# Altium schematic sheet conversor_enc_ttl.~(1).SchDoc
size A4
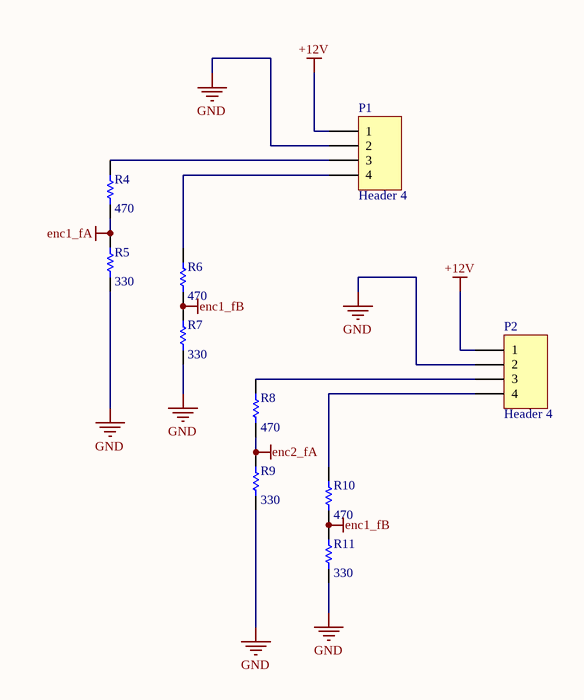
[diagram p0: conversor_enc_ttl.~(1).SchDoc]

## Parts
P1  Header 4  [HDR1X4]
P2  Header 4  [HDR1X4]
R4  value 470  [1005[0402]]  (hidden comment: metal film 2%)
R5  value 330  [1005[0402]]  (hidden comment: metal film 2%)
R6  value 470  [1005[0402]]  (hidden comment: metal film 2%)
R7  value 330  [1005[0402]]  (hidden comment: metal film 2%)
R8  value 470  [1005[0402]]  (hidden comment: metal film 2%)
R9  value 330  [1005[0402]]  (hidden comment: metal film 2%)
R10  value 470  [1005[0402]]  (hidden comment: metal film 2%)
R11  value 330  [1005[0402]]  (hidden comment: metal film 2%)

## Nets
+12V: P1.1 P2.1
enc1_fA: R4.1 R5.2
enc1_fB: R6.1 R7.2 R10.1 R11.2
enc2_fA: R8.1 R9.2
GND: P1.2 P2.2 R5.1 R7.1 R9.1 R11.1
NetP1_3: P1.3 R4.2
NetP1_4: P1.4 R6.2
NetP2_3: P2.3 R8.2
NetP2_4: P2.4 R10.2

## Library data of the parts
P1 P2 = Header 4: Header, 4-Pin
R4-R11 = Res Semi: Semiconductor Resistor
